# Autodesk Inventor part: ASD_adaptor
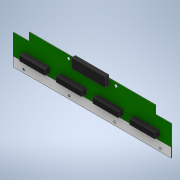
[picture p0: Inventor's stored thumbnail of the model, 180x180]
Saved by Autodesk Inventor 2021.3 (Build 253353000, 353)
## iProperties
Created: 2021-12
Part Number: ASD_adaptor
Material: 一般
Document SubType Name: Modeling
Designer: kengo
Density: 1 g/cm^3
Appearance: 既定
Author: kengo
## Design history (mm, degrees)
sketch "スケッチ1"
  geometry: L1 (-188.002, 84.58)-(61.998, 84.58); L2 (61.998, 84.58)-(61.998, 24.58); L3 (61.998, 24.58)-(-188.002, 24.58); L4 (-188.002, 24.58)-(-188.002, 84.58); L5 (-188.002, 84.58)-(-163.002, 84.58); L6 (-163.002, 84.58)-(-163.002, 71.58); L7 (-163.002, 71.58)-(-188.002, 71.58); L8 (-188.002, 71.58)-(-188.002, 84.58); L9 (36.998, 84.58)-(61.998, 84.58); L10 (61.998, 84.58)-(61.998, 71.58); L11 (61.998, 71.58)-(36.998, 71.58); L12 (36.998, 71.58)-(36.998, 84.58); 3 further points
  constraints: 24 end point, 6 parallel, 3 horizontal, 3 perpendicular, 3 point on line
  dimensions: "d0" = 250 distance of L2.end L3.end; "d1" = 60 distance of L1.end L2.end; "d2" = 13 distance of L5.end L6.end; "d3" = 25 distance of L6.end L7.end; "d4" = 25 distance of L10.end L11.end
extrude "押し出し1" new body sketch "スケッチ1" distance "d5" = 1; taper "d6" = 0 deg
sketch "スケッチ3"
  geometry: L1 (-188.002, 71.58)-(-188.002, 24.58) reference; L2 (-188.002, 24.58)-(61.998, 24.58) reference; L3 (-188.002, 39.58)-(61.998, 39.58); L4 (61.998, 39.58)-(61.998, 24.58); L5 (61.998, 24.58)-(-188.002, 24.58); L6 (-188.002, 24.58)-(-188.002, 39.58); 1 further point
  constraints: 8 end point, 2 parallel, 1 horizontal, 1 perpendicular, 1 point on line
  dimensions: "d23" = 15 distance between parallel lines of L2 L3
extrude "押し出し2" join sketch "スケッチ3" distance "d24" = 0.1; taper "d26" = 0 deg; dims "d25" = 1.1, "d27" = 0
sketch "スケッチ4" dims "d32" = 10
  geometry: L1 (-188.002, 39.58)-(-188.002, 24.58) reference; L2 (-188.002, 24.58)-(61.998, 24.58) reference; 5 further points
  constraints: 1 horizontal, 3 other
  dimensions: "d28" = 17 distance from line of L1 point (-171.002, 29.58); "d29" = 5 distance from line of L2 point (-171.002, 29.58); "d35" = 72 distance of point (-171.002, 29.58) point (-99.002, 29.58)
hole "穴2" sketch "スケッチ4" at (-171.002, 29.58), (-99.002, 29.58), (-27.002, 29.58), (44.998, 29.58) diameter "d37" = 3.2; stored, may be unused: countersink angle "d41" = 90 deg, drill point angle "d43" = 118 deg; dims "d38" = 6, "d39" = 4, "d40" = 2, "d42" = 100
sketch "スケッチ5" dims "d50" = 10
  geometry: L1 (-170.002, 53.58)-(-130.002, 53.58); L2 (-130.002, 53.58)-(-130.002, 45.58); L3 (-130.002, 45.58)-(-170.002, 45.58); L4 (-170.002, 45.58)-(-170.002, 53.58); L5 (61.998, 39.58)-(-188.002, 39.58) reference; L6 (-188.002, 71.58)-(-188.002, 39.58) reference; L7 (-112.002, 53.58)-(-72.002, 53.58); L8 (-72.002, 53.58)-(-72.002, 45.58); L9 (-72.002, 45.58)-(-112.002, 45.58); L10 (-112.002, 45.58)-(-112.002, 53.58); L11 (-54.002, 53.58)-(-14.002, 53.58); L12 (-14.002, 53.58)-(-14.002, 45.58); L13 (-14.002, 45.58)-(-54.002, 45.58); L14 (-54.002, 45.58)-(-54.002, 53.58); L15 (3.998, 53.58)-(43.998, 53.58); L16 (43.998, 53.58)-(43.998, 45.58); L17 (43.998, 45.58)-(3.998, 45.58); L18 (3.998, 45.58)-(3.998, 53.58); 1 further point
  constraints: 32 end point, 2 horizontal, 2 parallel, 1 perpendicular, 24 other
  dimensions: "d44" = 40 distance of L1.start L1.end; "d45" = 8 distance of L3.end L1.start; "d46" = 6 distance between parallel lines of L5 L3; "d47" = 18 distance between parallel lines of L6 L4; "d53" = 58 distance of L2.end L8.end
extrude "押し出し3" join sketch "スケッチ5" distance "d55" = 8; taper "d56" = 0 deg
sketch "スケッチ6"
  geometry: L1 (-89.502, 89.58)-(-36.502, 89.58); L2 (-36.502, 89.58)-(-36.502, 74.58); L3 (-36.502, 74.58)-(-89.502, 74.58); L4 (-89.502, 74.58)-(-89.502, 89.58); L5 (36.998, 71.58)-(36.998, 84.58) reference; L6 (36.998, 84.58)-(-163.002, 84.58) reference; 1 further point
  constraints: 8 end point, 2 parallel, 1 horizontal, 1 perpendicular
  dimensions: "d57" = 53 distance of L1.start L1.end; "d58" = 73.5 distance between parallel lines of L5 L2; "d59" = 15 distance of L1.end L2.end; "d60" = 5 distance between parallel lines of L6 L1
extrude "押し出し4" join sketch "スケッチ6" distance "d61" = 6; taper "d62" = 0 deg
sketch "スケッチ7"
  geometry: L1 (-89.502, 89.58)-(-89.502, 74.58) reference; L2 (36.998, 84.58)-(-36.502, 84.58) reference; L3 (-89.502, 84.58)-(-163.002, 84.58) reference; 3 further points
  dimensions: "d63" = 75 distance of point (-25.502, 79.58) point (-100.502, 79.58); "d64" = 11 distance from line of L1 point (-100.502, 79.58); "d65" = 5 distance from line of L2 point (-25.502, 79.58); "d66" = 5 distance from line of L3 point (-100.502, 79.58)
hole "穴3" sketch "スケッチ7" at (-100.502, 79.58), (-25.502, 79.58) diameter "d67" = 5; stored, may be unused: countersink angle "d71" = 90 deg, drill point angle "d73" = 118 deg; dims "d68" = 6, "d69" = 4, "d70" = 2, "d72" = 100
node "ソリッド1"
